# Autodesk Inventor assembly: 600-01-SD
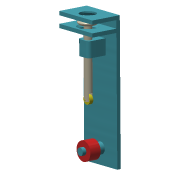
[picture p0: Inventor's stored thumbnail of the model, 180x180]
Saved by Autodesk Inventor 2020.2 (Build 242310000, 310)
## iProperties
Created: 2014-12
Part Number: 600-01-SD
Document SubType Name: Assembly
Designer: F.Stasiak
Catalog Web Link: www.expertbooks.pl
Manager: www.cadconsulting.pl
Company: Fabian Stasiak CAD Consulting
Author: F.Stasiak
Subject: Zbiór ćwiczeń. Autodesk Inventor 2020. Kurs Professional
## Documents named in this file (5)
- C:\2020_Kurs_Professional\R3 Dynamika\600-01-SD.iam
- C:\2020_Kurs_Professional\R3 Dynamika\Komponenty_dyn\Korpus_600.ipt
- C:\2020_Kurs_Professional\R3 Dynamika\Komponenty_dyn\Popychacz_600.ipt
- C:\2020_Kurs_Professional\R3 Dynamika\Komponenty_dyn\Krzywka_600.ipt
- C:\2020_Kurs_Professional\R3 Dynamika\Komponenty_dyn\Kółko_600.ipt
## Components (4 placed, 4 different names)
1. Korpus_600:1 — Równoległy:1, Wstaw:2, Zestawiający:1, PODNIESIENIE
2. Popychacz_600:1 — Zestawiający:1, PODNIESIENIE, Wstaw:3
3. Kółko_600:1 — Wstaw:3
4. Krzywka_600:1 — Równoległy:1, Wstaw:2
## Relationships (5: Insert 2, Mate 2, Flush 1)
- Równoległy:1 [Flush]: Korpus_600:1 ↔ Krzywka_600:1
- Wstaw:2 [Insert]: Korpus_600:1 ↔ Krzywka_600:1
- Zestawiający:1 [Mate]: Korpus_600:1 ↔ Popychacz_600:1
- PODNIESIENIE [Mate]: Korpus_600:1 ↔ Popychacz_600:1
- Wstaw:3 [Insert]: Popychacz_600:1 ↔ Kółko_600:1
